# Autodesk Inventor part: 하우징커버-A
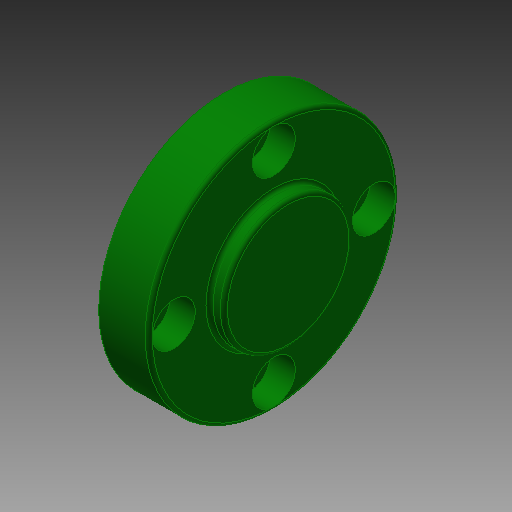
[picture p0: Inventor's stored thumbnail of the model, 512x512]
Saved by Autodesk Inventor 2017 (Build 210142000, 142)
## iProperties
Created: 2018-01
Part Number: 하우징커버-A
Material: 알루미늄 6061
Document SubType Name: Modeling
Designer: mduedu
Density: 2.71 g/cm^3
Mass: 18.1976 g
Surface Area: 30.9983 cm^2
Volume: 6.71499 cm^3
Appearance: 진녹색
Author: mduedu
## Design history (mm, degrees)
sketch "스케치1"
  geometry: C1 r 17.5 at (0, 0); 1 further point
  constraints: 1 centre point, 1 coincident
  dimensions: "d0" = 35 diameter of C1
extrude "돌출1" new body sketch "스케치1" distance "d1" = 7; taper "d2" = 0 deg
sketch "스케치2"
  geometry: C1 r 9 at (0, 0); 1 further point
  constraints: 1 centre point, 1 coincident
  dimensions: "d3" = 18 diameter of C1
extrude "돌출2" join sketch "스케치2" distance "d4" = 2; taper "d5" = 0 deg
fillet "모깎기1" dims "d6" = 0.5
fillet "모깎기2" dims "d7" = 0.5
sketch "스케치3" dims "d8" = 25
  geometry: 6 further points
  constraints: 2 vertical alignment, 1 coincident, 7 other
  dimensions: "d11" = 360 deg dimension on point (0, 0) point (0, 12.5) (derived)
sketch "스케치4"
  geometry: C1 r 17.5 at (0, 0) reference; A1 r 14 centre (0, 0) between (0, 14) and (14, 0); 2 further points
  constraints: 4 point on circle, 2 horizontal alignment, 2 vertical alignment, 1 centre point, 1 coincident
  dimensions: "d22" = 28 diameter of A1
hole "구멍1" sketch "스케치4" at (-14, 0), (0, -14), (14, 0), (0, 14) diameter "d13" = 3.4; stored, may be unused: countersink angle "d17" = 90 deg, drill point angle "d19" = 0 deg; dims "d14" = 6, "d15" = 6, "d16" = 3.5, "d18" = 8
node "솔리드1"
